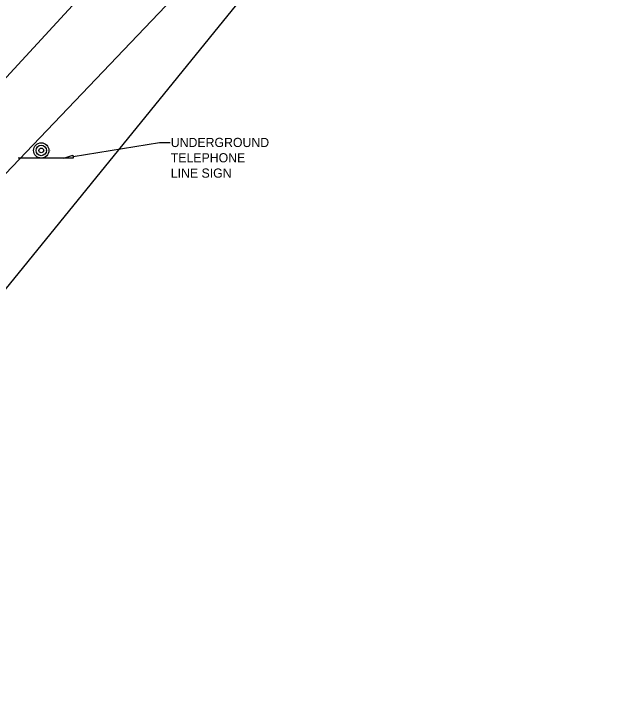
# Model space of a CAD drawing. Extents: x 2250985 to 2256614, y 13788366 to 13792478.
# Drawn here: x 2253266.2 to 2253344.7, y 13788998.9 to 13789089.1 of the extents above; entities that cross this region are included whole.
import ezdxf

# ---------------------------------------------------------------- set-up
doc = ezdxf.new("R2010")
doc.units = 0
for name, color, linetype in [('BORD_legend_plan_prof', 7, 'Continuous'), ('BORD_legend_sign', 7, 'Continuous'), ('BORD_legend_sign_screen', 7, 'Continuous'), ('BORD_seal_HM', 7, 'Continuous'), ('E_Drain_Culvert-Inside', 7, 'Continuous'), ('E_ROW_Driveway_3D_R', 7, 'Continuous'), ('E_Terrain_BoreHole', 7, 'Continuous')]:
    doc.layers.add(name, color=color, linetype=linetype)

# ---------------------------------------------------------------- blocks, each defined once
blk = doc.blocks.new('SGN')
at = {"layer": 'E_Drain_Culvert-Inside'}
blk.add_line((0.6, -0.2), (-0.6, -0.2), dxfattribs=at)
for radius in [0.2, 0.137, 0.0611]:
    blk.add_circle((0, 0), radius, dxfattribs=at)

msp = doc.modelspace()

# ---------------------------------------------------------------- linework, layer by layer
at = {"layer": 'BORD_seal_HM'}
msp.add_lwpolyline([(2253221.88, 13788998.86), (2253252.59, 13789037.79), (2253318.96, 13789119.44), (2253334.24, 13789137.43), (2253391.06, 13789195.24), (2253466.27, 13789272.27), (2253486.74, 13789294.54)], dxfattribs=at)
at = {"layer": 'E_ROW_Driveway_3D_R'}
for points in [[(2253201.37, 13789015.02), (2253237.34, 13789050.58), (2253308.73, 13789128.07), (2253383.08, 13789203.04), (2253459.19, 13789278.49), (2253481.57, 13789299.81)], [(2253211.05, 13789011.44), (2253243.15, 13789045.28), (2253316.06, 13789121.59), (2253390.03, 13789195.97), (2253465.17, 13789272.89), (2253483.94, 13789292.24), (2253484.2, 13789298.46), (2253482.83, 13789300.18)]]:
    msp.add_lwpolyline(points, dxfattribs=at)
msp.add_spline([(2253199.79, 13789023.57), (2253231.26, 13789055.67), (2253305.08, 13789131.6), (2253378.64, 13789207.45), (2253453.2, 13789283.87)], degree=3, dxfattribs=at)
at = {"layer": 'E_Terrain_BoreHole'}
msp.add_line((2253285.175, 13789072.274), (2253286.575, 13789072.274), dxfattribs=at)
msp.add_lwpolyline([(2253273.905, 13789070.424), (2253285.175, 13789072.274)], dxfattribs=at)
msp.add_lwpolyline([(2253273.938, 13789070.227), (2253272.721, 13789070.23), (2253273.873, 13789070.622)], close=True, dxfattribs=at)

# ---------------------------------------------------------------- block references
at = {"layer": 'E_Drain_Culvert-Inside', "xscale": 5, "yscale": 5}
msp.add_blockref('SGN', (2253269.76, 13789071.23), dxfattribs=at)

# ---------------------------------------------------------------- texts
at = {"layer": 'BORD_legend_plan_prof'}
msp.add_text('5630', height=0.06, dxfattribs=at).set_placement((2253269.885, 13789071.355))
at = {"layer": 'BORD_legend_sign'}
msp.add_text('662.76', height=0.06, dxfattribs=at).set_placement((2253269.885, 13789071.045))
at = {"layer": 'BORD_legend_sign_screen'}
msp.add_text('UNDERGROUND TELEPHONE LINE SIGN', height=0.06, dxfattribs=at).set_placement((2253269.885, 13789071.2))
at = {"layer": 'E_Terrain_BoreHole'}
for s, p in [('UNDERGROUND ', (2253286.665, 13789071.674)), ('TELEPHONE ', (2253286.665, 13789069.674)), ('LINE SIGN', (2253286.665, 13789067.674))]:
    msp.add_text(s, height=1.2, dxfattribs=at).set_placement(p)

doc.saveas('drawing.dxf')
